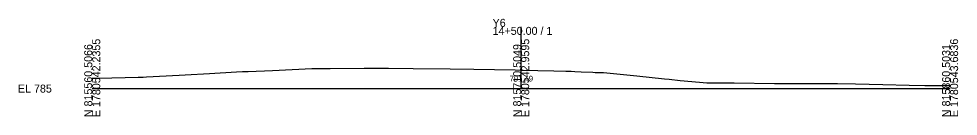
# Model space of a CAD drawing. Extents: x -26 to 1603, y -10 to 6024.
# Drawn here: x -25.7 to 302.8, y 5990.3 to 6024.5 of the extents above; entities that cross this region are included whole.
import ezdxf

# ---------------------------------------------------------------- set-up
doc = ezdxf.new("R2010")
doc.units = 0
for name, color, linetype in [('Exist Cross Section Cell', 7, 'Continuous'), ('Exist XS Center Line Elevation Label', 7, 'Continuous'), ('Exist XS Ground Line', 7, 'Continuous')]:
    doc.layers.add(name, color=color, linetype=linetype)

msp = doc.modelspace()

# ---------------------------------------------------------------- linework, layer by layer
at = {"layer": 'Exist Cross Section Cell'}
for p, q in [((150, 6000), (150, 6021.64)), ((0, 6000), (150, 6000)), ((150, 6000), (300, 6000))]:
    msp.add_line(p, q, dxfattribs=at)
at = {"layer": 'Exist XS Ground Line'}
for p, q in [((41.04, 6005.32), (50.5, 6005.85)), ((50.5, 6005.85), (52.49, 6005.96)), ((52.49, 6005.96), (54.49, 6006.03)), ((54.49, 6006.03), (63.07, 6006.33)), ((63.07, 6006.33), (76.77, 6007.02)), ((76.77, 6007.02), (81.83, 6007.04)), ((81.83, 6007.04), (82.41, 6007.04)), ((82.41, 6007.04), (83.23, 6007.05)), ((83.23, 6007.05), (95.12, 6007.14)), ((95.12, 6007.14), (103.61, 6007.21)), ((103.61, 6007.21), (112.18, 6007.1)), ((112.18, 6007.1), (125.18, 6006.92)), ((125.18, 6006.92), (133.45, 6006.77)), ((133.45, 6006.77), (147.85, 6006.54)), ((147.85, 6006.54), (150, 6006.49)), ((150, 6006.49), (150.72, 6006.48)), ((150.72, 6006.48), (155.86, 6006.36)), ((155.86, 6006.36), (161.37, 6006.2)), ((161.37, 6006.2), (165.67, 6006.08)), ((165.67, 6006.08), (167.45, 6006.06)), ((167.45, 6006.06), (168.73, 6005.96)), ((168.73, 6005.96), (170.96, 6005.87)), ((170.96, 6005.87), (175.06, 6005.72)), ((175.06, 6005.72), (175.92, 6005.69)), ((175.92, 6005.69), (177.43, 6005.64)), ((177.43, 6005.64), (178.75, 6005.61)), ((178.75, 6005.61), (190.39, 6004.51)), ((0, 6003.63), (1.99, 6003.66)), ((1.99, 6003.66), (2.3, 6003.66)), ((2.3, 6003.66), (16.11, 6003.98)), ((16.11, 6003.98), (17.81, 6004.06)), ((17.81, 6004.06), (18.98, 6004.12)), ((18.98, 6004.12), (30.45, 6004.74)), ((30.45, 6004.74), (32.47, 6004.85)), ((32.47, 6004.85), (41.04, 6005.32)), ((190.39, 6004.51), (200.08, 6003.44)), ((200.08, 6003.44), (201.77, 6003.25)), ((201.77, 6003.25), (205.59, 6002.87)), ((205.59, 6002.87), (212.42, 6002.24)), ((212.42, 6002.24), (214.9, 6001.98)), ((214.9, 6001.98), (223.41, 6002.01)), ((223.41, 6002.01), (224.5, 6001.99)), ((224.5, 6001.99), (238.56, 6001.81)), ((238.56, 6001.81), (240.05, 6001.78)), ((240.05, 6001.78), (241.81, 6001.79)), ((241.81, 6001.79), (243.9, 6001.79)), ((243.9, 6001.79), (249.76, 6001.73)), ((249.76, 6001.73), (256.17, 6001.75)), ((256.17, 6001.75), (260.57, 6001.74)), ((260.57, 6001.74), (266.93, 6001.65)), ((266.93, 6001.65), (276.44, 6001.46)), ((276.44, 6001.46), (285.63, 6001.25)), ((285.63, 6001.25), (291.2, 6001.13)), ((291.2, 6001.13), (300, 6001.04))]:
    msp.add_line(p, q, dxfattribs=at)

# ---------------------------------------------------------------- texts
at = {"layer": 'Exist Cross Section Cell'}
for s, p in [('Y6', (140, 6021.64)), ('14+50.00 / 1', (140, 6018.84)), ('EL 785', (-26, 5998.6))]:
    msp.add_text(s, height=2.8, dxfattribs=at).set_placement(p)
for s, p in [('N 815560.5066', (0, 5990)), ('E 1780542.2355', (2.8, 5990)), ('E 1780542.9595', (152.8, 5990)), ('E 1780543.6836', (302.8, 5990)), ('N 815710.5049', (150, 5990)), ('N 815860.5031', (300, 5990))]:
    msp.add_text(s, height=2.8, rotation=90, dxfattribs=at).set_placement(p)
at = {"layer": 'Exist XS Center Line Elevation Label'}
msp.add_text('791.49', height=2, dxfattribs=at).set_placement((145.97, 6002.49))

doc.saveas('drawing.dxf')
